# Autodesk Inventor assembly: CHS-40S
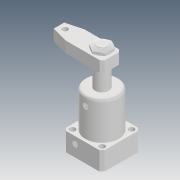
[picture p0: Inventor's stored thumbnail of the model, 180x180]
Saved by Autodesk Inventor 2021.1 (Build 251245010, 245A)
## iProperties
Created: 2019-04
Part Number: CHS-40S
Description: STEP AP203
Document SubType Name: Assembly
Designer: user
Title: chs-40s_asm.STEP
Revision Number: ÈÎºÎ
Sending System: SolidWorks 2017
Preprocessor: SwSTEP 2.0
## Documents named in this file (5)
- D:\Vault_2016\Projekty\Clamptek\Hydraulic\CHS\CHS-40\Inventor\CHS-40S\CHS-40S.iam
- D:\Vault_2016\Projekty\Clamptek\Hydraulic\CHS\CHS-40\Inventor\CHS-40S\CHS-40-03_1.ipt
- D:\Vault_2016\Projekty\Clamptek\Hydraulic\CHS\CHS-40\Inventor\CHS-40S\CHS-40S-02.ipt
- D:\Vault_2016\Projekty\Clamptek\Hydraulic\CHS\CHS-40\Inventor\CHS-40S\CHS-40S-01.ipt
- D:\Vault_2016\Projekty\Clamptek\Hydraulic\CHS\CHS-40\Inventor\CHS-40S\M18.ipt
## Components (4 placed, 4 different names)
1. CHS-40-03_1_1
2. CHS-40S-02_2
3. CHS-40S-01_3
4. M18_4
